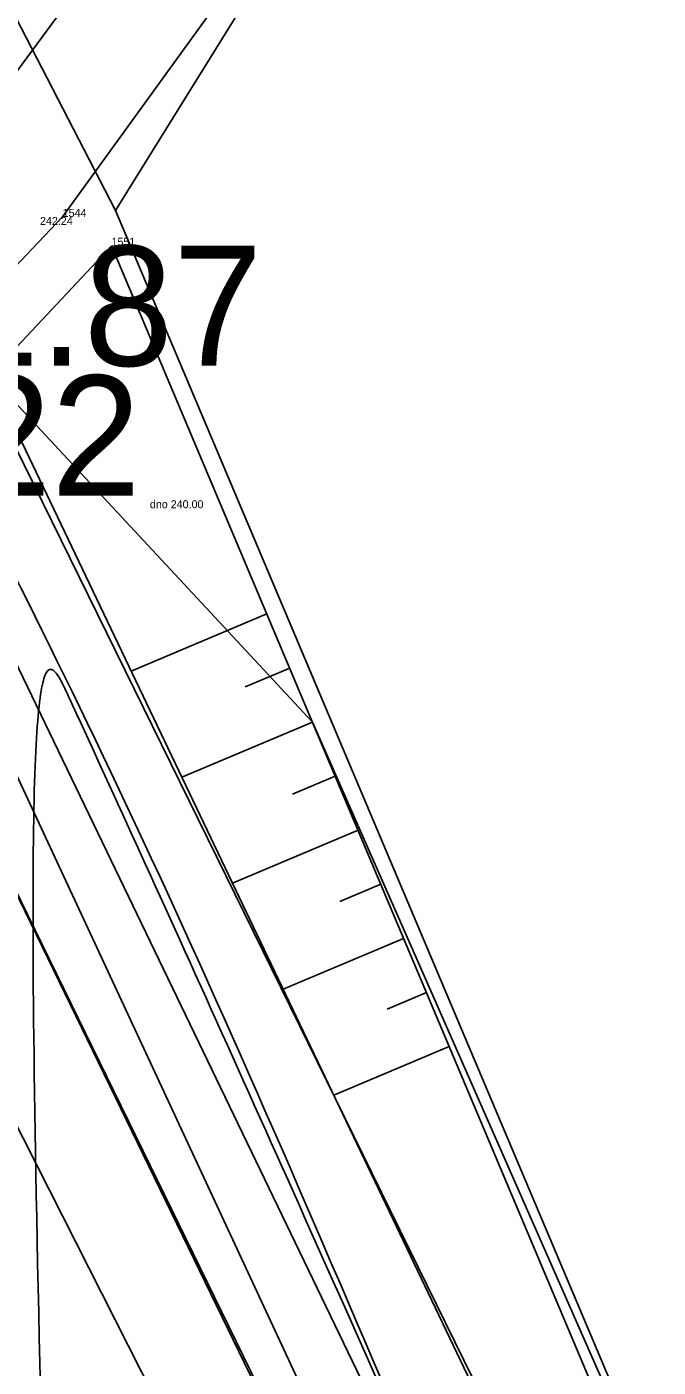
# Model space of a CAD drawing. Extents: x -555757 to -553364, y -1100723 to -1096439.
# Drawn here: x -553835.95 to -553828.06, y -1098324.05 to -1098307.3 of the extents above; entities that cross this region are included whole.
import ezdxf

# ---------------------------------------------------------------- set-up
doc = ezdxf.new("R2010")
doc.units = 0
for name, color, linetype in [('00_NÁVRH - 0.18 mm', 7, 'Continuous'), ('00_NÁVRH - 0.35 mm', 7, 'Continuous'), ('01_HLADINA', 7, 'Continuous'), ('Geodet. výšky - netisknuté', 7, 'Continuous'), ('HRANA$SVAHU', 7, 'Continuous'), ('HRANICE$PARCELY', 7, 'Continuous'), ('OSA$KOLEJI', 7, 'Continuous'), ('ROZHRANI', 7, 'Continuous'), ('VOZOVKA', 7, 'Continuous'), ('VYSKA_PODR_BOD', 7, 'Continuous'), ('VYSKOVE$SRAFY', 7, 'Continuous'), ('zájem', 7, 'Continuous')]:
    doc.layers.add(name, color=color, linetype=linetype)

# ---------------------------------------------------------------- blocks, each defined once
blk = doc.blocks.new('POINT_DISPLAY')
blk.add_line((0, 0), (0, 0))

msp = doc.modelspace()

# ---------------------------------------------------------------- linework, layer by layer
at = {"layer": '00_NÁVRH - 0.18 mm'}
for points in [[(-553818.319, -1098411.071), (-553817.252, -1098377.047), (-553817.288, -1098376.437), (-553817.447, -1098375.777), (-553823.472, -1098341.426), (-553837.491, -1098312.335), (-553844.813, -1098299.382), (-553849.765, -1098286.744), (-553862.789, -1098239.707), (-553871.864, -1098218.379), (-553882.658, -1098190.488), (-553893.712, -1098159.188)], [(-553843.18, -1098601.405), (-553834.399, -1098572.997), (-553828.319, -1098553.123), (-553826.37, -1098545.911), (-553826.292, -1098545.016), (-553826.171, -1098543.852), (-553822.125, -1098515.091), (-553818, -1098485.77), (-553817.988, -1098484.316), (-553817.76, -1098456.45), (-553816.78, -1098411.27), (-553816.738, -1098409.15), (-553816.07, -1098377.627), (-553816.142, -1098375.858), (-553816.289, -1098374.477), (-553821.019, -1098345.557), (-553821.739, -1098340.281), (-553822.216, -1098339.073), (-553832.38, -1098315.991), (-553836.41, -1098311.66)], [(-553819.814, -1098409.075), (-553819.018, -1098377.607), (-553818.99, -1098376.48), (-553822.732, -1098353.444), (-553824.65, -1098341.64), (-553825.26, -1098340.241), (-553838.36, -1098313.45)]]:
    msp.add_lwpolyline(points, dxfattribs=at)
at = {"layer": '00_NÁVRH - 0.35 mm'}
msp.add_lwpolyline([(-553891.142, -1098770.791), (-553891.715, -1098743.444), (-553891.785, -1098741.233), (-553891.732, -1098740.932), (-553891.62, -1098740.61), (-553883.127, -1098714.681), (-553874.569, -1098686.698), (-553864.003, -1098657.766), (-553854.187, -1098630.741), (-553844.771, -1098600.952), (-553838.301, -1098579.033), (-553828.043, -1098545.053), (-553827.742, -1098543.434), (-553827.432, -1098541.887), (-553819.514, -1098485.675), (-553819.443, -1098484.053), (-553819.471, -1098455.973), (-553818.757, -1098409.101), (-553817.856, -1098377.169), (-553817.973, -1098376.271), (-553818.122, -1098375.61), (-553824.446, -1098341.733), (-553825.12, -1098340.187), (-553837.804, -1098312.944)], dxfattribs=at)
msp.add_open_spline([(-553794.11, -1099299.314), (-553795.302, -1099298.083), (-553795.885, -1099297.697), (-553798.014, -1099296.378), (-553798.648, -1099296.009), (-553799.057, -1099295.868), (-553800.013, -1099295.626), (-553800.97, -1099295.434), (-553803.916, -1099294.978), (-553807.943, -1099294.404), (-553820.006, -1099292.714), (-553824.218, -1099292.087), (-553827.541, -1099291.556), (-553834.292, -1099290.18), (-553840, -1099289.072), (-553843.606, -1099288.311), (-553846.032, -1099287.854), (-553848.004, -1099287.449), (-553849.388, -1099287.281), (-553865.944, -1099285.252), (-553871.048, -1099284.805), (-553873.856, -1099284.514), (-553874.399, -1099284.43), (-553876.775, -1099283.969), (-553879.064, -1099283.332), (-553880.051, -1099283.031), (-553881.093, -1099282.392), (-553882.188, -1099281.754), (-553883.228, -1099281.083), (-553884.328, -1099279.969), (-553885.547, -1099278.713), (-553889.777, -1099274.4), (-553901.548, -1099262.428), (-553911.972, -1099251.719), (-553924.19, -1099239.3), (-553934.53, -1099228.739), (-553940.93, -1099222.274), (-553947.073, -1099216.541), (-553953.84, -1099210.491), (-553956.731, -1099207.941), (-553957.05, -1099207.628), (-553964.746, -1099199.605), (-553968.133, -1099195.981), (-553972.842, -1099191.048), (-553973.281, -1099190.444), (-553973.656, -1099189.74), (-553976.661, -1099181.556), (-553981.28, -1099169.188), (-553982.799, -1099164.023), (-553982.956, -1099163.184), (-553982.84, -1099162.204), (-553982.616, -1099160.636), (-553981.347, -1099154.446), (-553980.688, -1099150.992), (-553979.675, -1099146.656), (-553979.439, -1099145.68), (-553978.925, -1099144.071), (-553976.623, -1099137.958), (-553971.496, -1099124.445), (-553956.509, -1099083.004), (-553948.349, -1099063.109), (-553947.145, -1099060.166), (-553946.295, -1099057.429), (-553943.525, -1099049.31), (-553939.704, -1099037.846), (-553934.366, -1099021.961), (-553930.78, -1099011.15), (-553926.744, -1098998.785), (-553924.694, -1098992.816), (-553921.255, -1098983.982), (-553917.56, -1098974.667), (-553914.06, -1098965.564), (-553908.691, -1098951.909), (-553901.821, -1098934.804), (-553901.394, -1098933.668), (-553901.099, -1098932.553), (-553900.651, -1098929.575), (-553899.921, -1098923.604), (-553898.961, -1098915.482), (-553898.391, -1098910.691), (-553898.127, -1098908.396), (-553898.218, -1098907.183), (-553898.459, -1098905.433), (-553899.12, -1098901.506), (-553900.514, -1098893.561), (-553900.636, -1098892.888), (-553900.544, -1098892.328), (-553900.228, -1098891.412), (-553899.451, -1098889.266), (-553897.423, -1098883.769), (-553893.021, -1098871.924), (-553886.932, -1098855.681), (-553885.605, -1098852.197), (-553884.629, -1098849.656), (-553884.106, -1098848.151), (-553883.861, -1098847.39), (-553883.788, -1098846.997), (-553883.77, -1098846.594), (-553883.802, -1098846.171), (-553883.858, -1098845.819), (-553884.325, -1098844.246), (-553887.679, -1098834.274), (-553890.606, -1098825.191), (-553891.018, -1098823.527), (-553891.066, -1098823.121), (-553891.005, -1098822.697), (-553890.8, -1098821.707), (-553890.203, -1098818.823), (-553888.001, -1098807.301), (-553885.789, -1098795.251), (-553885.363, -1098792.934), (-553885.23, -1098792.173), (-553885.147, -1098791.711), (-553885.147, -1098791.302), (-553885.151, -1098791.006), (-553885.22, -1098790.609), (-553886.502, -1098784.837), (-553888.275, -1098776.483), (-553889.523, -1098771.371), (-553889.704, -1098770.489), (-553889.76, -1098769.236), (-553890.011, -1098761.77), (-553890.328, -1098747.9), (-553890.415, -1098743.459), (-553890.422, -1098742.114), (-553890.412, -1098741.338), (-553890.227, -1098740.638), (-553887.44, -1098731.802), (-553883.473, -1098718.833), (-553877.882, -1098700.91), (-553873.654, -1098687.07), (-553869.067, -1098673.807), (-553863.431, -1098657.948), (-553859.616, -1098647.384), (-553854.518, -1098632.992), (-553853.778, -1098630.91), (-553852.903, -1098628.215), (-553851.147, -1098622.78), (-553848.209, -1098613.648), (-553844.194, -1098601.116), (-553841.044, -1098590.723), (-553837.173, -1098577.952), (-553835.011, -1098570.679), (-553833.035, -1098564.139), (-553830.71, -1098556.281), (-553828.586, -1098548.945), (-553827.55, -1098545.495), (-553827.333, -1098544.629), (-553827.114, -1098543.601), (-553826.943, -1098542.73), (-553826.694, -1098541.466), (-553826.528, -1098540.348), (-553825.375, -1098531.946), (-553823.552, -1098519.221), (-553822.413, -1098510.953), (-553821.269, -1098503.56), (-553820.357, -1098496.716), (-553819.264, -1098489.108), (-553818.909, -1098486.041), (-553818.853, -1098485.532), (-553818.848, -1098485.156), (-553818.852, -1098484.16), (-553818.788, -1098477.885), (-553818.638, -1098467.214), (-553818.464, -1098454.698), (-553818.096, -1098433.157), (-553817.825, -1098416.015), (-553817.758, -1098409.125), (-553817.716, -1098406.971), (-553817.481, -1098400.257), (-553817.113, -1098388.412), (-553816.885, -1098378.571), (-553816.924, -1098376.341), (-553817.085, -1098375.505), (-553817.655, -1098372.671), (-553823.7, -1098343.15), (-553824.052, -1098341.595), (-553824.653, -1098340.008), (-553827.064, -1098334.584), (-553831.231, -1098324.895), (-553836.053, -1098314.241), (-553837.067, -1098312.263), (-553794.638, -1099298.639), (-553836.551, -1098313.247)], degree=3, dxfattribs=at)
at = {"layer": '01_HLADINA'}
msp.add_line((-553837.804, -1098312.944), (-553825.12, -1098340.187), dxfattribs=at)
msp.add_open_spline([(-553823.796, -1098342.663), (-553823.868, -1098342.303), (-553824.072, -1098341.393), (-553825.194, -1098338.696), (-553827.73, -1098333.201), (-553831.36, -1098324.536), (-553834.604, -1098317.042), (-553836.723, -1098312.92), (-553837.067, -1098312.263)], degree=3, dxfattribs=at)
at = {"layer": 'HRANA$SVAHU'}
for p, q in [((-553821.77, -1098341.14), (-553834.89, -1098310.04)), ((-553822.3, -1098341.18), (-553836.41, -1098311.66)), ((-553838.36, -1098313.45), (-553824.65, -1098341.64)), ((-553839.42, -1098314.43), (-553825.55, -1098341.8))]:
    msp.add_line(p, q, dxfattribs=at)
at = {"layer": 'HRANICE$PARCELY'}
for q in [(-553834.61, -1098305.88), (-553824.61, -1098335.92)]:
    msp.add_line((-553837.47, -1098309.75), q, dxfattribs=at)
at = {"layer": 'ROZHRANI'}
msp.add_line((-553834.89, -1098310.04), (-553836.41, -1098311.66), dxfattribs=at)
at = {"layer": 'VOZOVKA'}
for p, q in [((-553835.5, -1098309.68), (-553833.12, -1098306.39)), ((-553840.87, -1098315.32), (-553835.5, -1098309.68))]:
    msp.add_line(p, q, dxfattribs=at)
at = {"layer": 'VYSKOVE$SRAFY'}
for p, q in [((-553832.949, -1098314.64), (-553834.644, -1098315.356)), ((-553832.664, -1098315.315), (-553833.219, -1098315.549)), ((-553832.38, -1098315.991), (-553834.011, -1098316.679)), ((-553832.095, -1098316.666), (-553832.628, -1098316.891)), ((-553831.81, -1098317.341), (-553833.378, -1098318.003)), ((-553831.525, -1098318.017), (-553832.038, -1098318.232)), ((-553831.24, -1098318.692), (-553832.746, -1098319.326)), ((-553830.955, -1098319.367), (-553831.446, -1098319.575)), ((-553830.67, -1098320.043), (-553832.113, -1098320.651))]:
    msp.add_line(p, q, dxfattribs=at)
at = {"layer": 'zájem'}
for points in [[(-553796.85, -1098169.41), (-553801.19, -1098189.94), (-553796.69, -1098202.96), (-553790.97, -1098202.46), (-553787.94, -1098222.03), (-553776.83, -1098226.45), (-553774.8, -1098233.56), (-553779.33, -1098244.73), (-553793.5, -1098257.9), (-553796.19, -1098265.28), (-553801.93, -1098280.68), (-553811.08, -1098291.9), (-553813.65, -1098304.59), (-553832.93, -1098306.52), (-553834.84, -1098309.6), (-553837.04, -1098305.33), (-553848.93, -1098273.99), (-553857.57, -1098247.87), (-553865.26, -1098222.5), (-553872.03, -1098204), (-553873.38, -1098200.91), (-553884.8, -1098171.23)], [(-553884.8, -1098171.23), (-553873.38, -1098200.91), (-553872.03, -1098204), (-553865.26, -1098222.5), (-553857.57, -1098247.87), (-553848.93, -1098273.99), (-553837.04, -1098305.33), (-553834.84, -1098309.6), (-553822.39, -1098339.05), (-553816.99, -1098366.76), (-553819.71, -1098517.47)], [(-553819.71, -1098517.47), (-553816.99, -1098366.76), (-553822.39, -1098339.05), (-553834.84, -1098309.6), (-553832.93, -1098306.52), (-553813.65, -1098304.59), (-553811.08, -1098291.9), (-553801.93, -1098280.68), (-553796.19, -1098265.28), (-553793.5, -1098257.9)]]:
    msp.add_lwpolyline(points, dxfattribs=at)

# ---------------------------------------------------------------- block references
at = {"layer": 'ROZHRANI'}
for p in [(-553835.5, -1098309.68), (-553834.89, -1098310.04)]:
    msp.add_blockref('POINT_DISPLAY', p, dxfattribs=at)

# ---------------------------------------------------------------- texts
at = {"layer": 'Geodet. výšky - netisknuté'}
for s, p in [('242.24', (-553835.783, -1098309.78)), ('dno 240.00', (-553834.41, -1098313.319))]:
    msp.add_text(s, height=0.1, dxfattribs=at).set_placement(p)
at = {"layer": 'OSA$KOLEJI'}
for s, p in [('1544', (-553835.5, -1098309.68)), ('1551', (-553834.89, -1098310.04))]:
    msp.add_text(s, height=0.1, dxfattribs=at).set_placement(p)
at = {"layer": 'VYSKA_PODR_BOD'}
for s, p in [('241.87', (-553839.14, -1098311.54)), ('240.22', (-553840.66, -1098313.16))]:
    msp.add_text(s, height=1.5, dxfattribs=at).set_placement(p)

doc.saveas('drawing.dxf')
